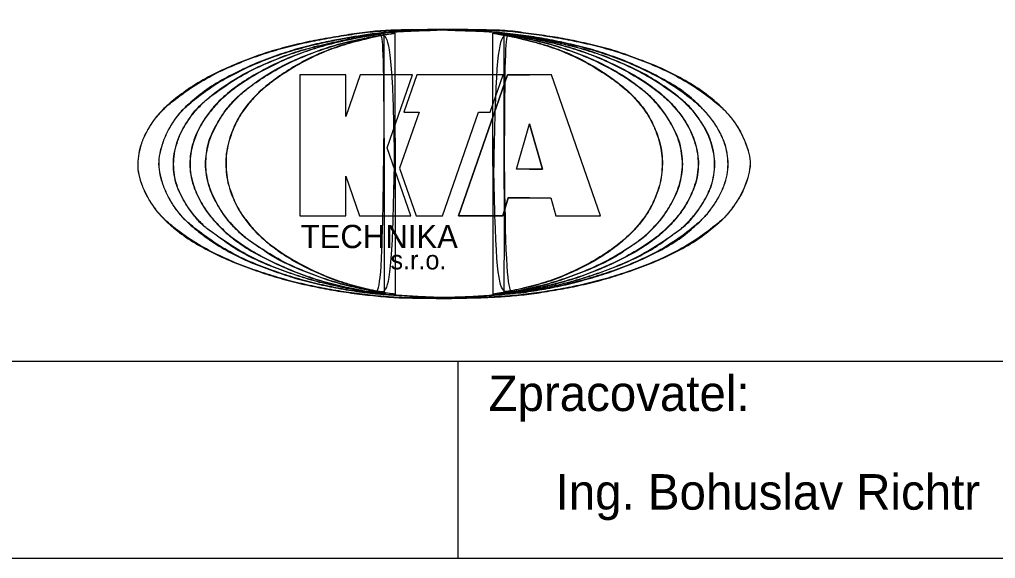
# Model space of a CAD drawing. Extents: x -729968 to -728918, y -1073811 to -1072326.
# Drawn here: x -729327.8 to -729080.2, y -1073351.1 to -1073214.6 of the extents above; entities that cross this region are included whole.
import ezdxf

# ---------------------------------------------------------------- set-up
doc = ezdxf.new("R2010")
doc.units = 0
doc.layers.add('_popis', color=7, linetype='Continuous')
doc.layers.add('Rozpiska_pole_6', color=7, linetype='Continuous')

msp = doc.modelspace()

# ---------------------------------------------------------------- linework, layer by layer
at = {"layer": '_popis'}
for p, q in [((-729198.42, -1073241.01), (-729195.1, -1073252.49)), ((-729195.1, -1073252.49), (-729198.42, -1073252.49))]:
    msp.add_line(p, q, dxfattribs=at)
for points in [[(-729256.7, -1073228.58), (-729256.7, -1073264.29), (-729245.02, -1073264.29), (-729245.02, -1073254.22), (-729241.52, -1073264.29), (-729228.52, -1073264.29), (-729234.52, -1073247.06), (-729228.09, -1073228.58), (-729241.34, -1073228.58), (-729245.02, -1073239.17), (-729245.02, -1073228.58), (-729256.7, -1073228.58)], [(-729256.7, -1073228.58), (-729256.7, -1073264.29), (-729245.02, -1073264.29), (-729245.02, -1073254.22), (-729241.52, -1073264.29), (-729228.52, -1073264.29), (-729234.52, -1073247.06), (-729228.09, -1073228.58), (-729241.34, -1073228.58), (-729245.02, -1073239.17), (-729245.02, -1073228.58), (-729256.7, -1073228.58)], [(-729227.02, -1073228.58), (-729230.3, -1073238.02), (-729226.42, -1073238.02), (-729231.36, -1073252.21), (-729227.16, -1073264.29), (-729220.51, -1073264.29), (-729211.37, -1073238.02), (-729208.35, -1073238.02), (-729205.06, -1073228.58), (-729227.02, -1073228.58)], [(-729227.02, -1073228.58), (-729230.3, -1073238.02), (-729226.42, -1073238.02), (-729231.36, -1073252.21), (-729227.16, -1073264.29), (-729220.51, -1073264.29), (-729211.37, -1073238.02), (-729208.35, -1073238.02), (-729205.06, -1073228.58), (-729227.02, -1073228.58)], [(-729198.42, -1073259.72), (-729203.83, -1073259.72), (-729205.15, -1073264.29), (-729216.42, -1073264.28), (-729203.99, -1073228.58), (-729198.42, -1073228.58)], [(-729198.42, -1073228.58), (-729203.99, -1073228.58), (-729216.42, -1073264.28), (-729205.15, -1073264.29), (-729203.83, -1073259.72), (-729198.42, -1073259.72)], [(-729198.42, -1073259.72), (-729193.01, -1073259.72), (-729191.69, -1073264.29), (-729180.43, -1073264.28), (-729192.85, -1073228.58), (-729198.42, -1073228.58)], [(-729198.42, -1073259.72), (-729193.01, -1073259.72), (-729191.69, -1073264.29), (-729180.43, -1073264.28), (-729192.85, -1073228.58), (-729198.42, -1073228.58)], [(-729198.42, -1073252.49), (-729201.74, -1073252.49), (-729198.42, -1073241.01)], [(-729198.42, -1073252.49), (-729201.74, -1073252.49), (-729198.42, -1073241.01)], [(-729198.42, -1073252.49), (-729195.1, -1073252.49), (-729198.42, -1073241.01)]]:
    msp.add_lwpolyline(points, dxfattribs=at)
for points in [[(-729220.07, -1073217.05), (-729222.09, -1073217.09), (-729225.67, -1073217.14), (-729231.03, -1073217.18), (-729236.17, -1073217.36), (-729241.53, -1073217.93), (-729246.88, -1073218.83), (-729252.26, -1073219.71), (-729257.63, -1073220.87), (-729263.01, -1073222.26), (-729268.39, -1073224.01), (-729273.74, -1073226.17), (-729279.19, -1073228.61), (-729284.59, -1073231.83), (-729288.82, -1073234.98), (-729292.04, -1073237.91), (-729294.02, -1073240.37), (-729295.67, -1073243.1), (-729296.94, -1073245.77), (-729297.53, -1073248.51), (-729297.93, -1073251.2), (-729297.6, -1073253.94), (-729296.75, -1073256.62), (-729295.56, -1073259.36), (-729293.8, -1073262.03), (-729291.93, -1073264.48), (-729288.75, -1073267.34), (-729284.65, -1073270.51), (-729279.15, -1073273.5), (-729273.79, -1073276.04), (-729268.37, -1073278.03), (-729263, -1073279.79), (-729257.64, -1073281.26), (-729252.28, -1073282.42), (-729246.92, -1073283.41), (-729241.53, -1073284.16), (-729236.17, -1073284.75), (-729230.8, -1073285.17), (-729225.44, -1073285.11), (-729220.07, -1073285.3), (-729214.71, -1073285.13), (-729210.61, -1073285.08), (-729208.3, -1073284.96), (-729207.78, -1073284.93)], [(-729220.07, -1073217.05), (-729226.13, -1073217.14), (-729230.79, -1073217.2), (-729236.15, -1073217.42), (-729241.51, -1073217.98), (-729246.87, -1073218.82), (-729252.24, -1073219.75), (-729257.6, -1073220.9), (-729262.96, -1073222.31), (-729268.33, -1073224.06), (-729273.69, -1073226.19), (-729279.02, -1073228.66), (-729284.39, -1073231.83), (-729289.75, -1073235.87), (-729291.84, -1073237.82), (-729294.02, -1073240.51), (-729295.65, -1073243.17), (-729296.86, -1073245.86), (-729297.5, -1073248.53), (-729297.81, -1073251.22), (-729297.53, -1073253.86), (-729296.72, -1073256.57), (-729295.51, -1073259.26), (-729293.83, -1073261.92), (-729291.67, -1073264.62), (-729289.76, -1073266.4), (-729284.4, -1073270.47), (-729279.04, -1073273.5), (-729273.74, -1073275.97), (-729268.32, -1073278.01), (-729262.94, -1073279.76), (-729257.61, -1073281.22), (-729252.28, -1073282.39), (-729246.89, -1073283.38), (-729241.52, -1073284.14), (-729236.13, -1073284.73), (-729230.83, -1073285.09), (-729225.43, -1073285.15), (-729220.07, -1073285.24), (-729214.71, -1073285.15), (-729209.34, -1073285.01), (-729203.98, -1073284.67), (-729198.65, -1073284.17), (-729193.27, -1073283.35), (-729187.91, -1073282.4), (-729182.55, -1073281.2), (-729177.18, -1073279.71), (-729171.82, -1073277.94), (-729166.46, -1073275.87), (-729161.13, -1073273.37), (-729155.73, -1073270.21), (-729150.34, -1073266.03), (-729148.74, -1073264.6), (-729146.64, -1073261.94), (-729144.87, -1073259.28), (-729143.63, -1073256.57), (-729142.76, -1073253.91), (-729142.33, -1073251.22), (-729142.65, -1073248.55), (-729143.57, -1073245.85), (-729144.78, -1073243.12), (-729146.38, -1073240.51), (-729148.65, -1073237.82), (-729150.3, -1073236.19), (-729155.72, -1073232), (-729161.08, -1073228.83), (-729166.4, -1073226.29), (-729171.79, -1073224.22), (-729177.18, -1073222.37), (-729182.51, -1073220.96), (-729187.91, -1073219.76), (-729193.3, -1073218.83), (-729198.68, -1073218.07), (-729204, -1073217.4), (-729209.35, -1073217.2), (-729214.7, -1073217.11), (-729220.07, -1073217.05), (-729220.07, -1073217.05), (-729220.07, -1073217.05)], [(-729220.07, -1073217.2), (-729218.28, -1073217.27), (-729214.7, -1073217.42), (-729209.33, -1073217.47), (-729203.98, -1073218.06), (-729198.62, -1073218.74), (-729193.24, -1073219.63), (-729187.89, -1073220.82), (-729182.48, -1073222.1), (-729177.13, -1073223.92), (-729171.72, -1073225.99), (-729166.38, -1073228.63), (-729160.8, -1073231.63), (-729156.69, -1073234.91), (-729153.64, -1073237.96), (-729151.72, -1073240.39), (-729150.07, -1073243.1), (-729148.84, -1073245.79), (-729148.2, -1073248.52), (-729147.97, -1073251.23), (-729148.17, -1073253.96), (-729148.99, -1073256.65), (-729150.19, -1073259.35), (-729151.9, -1073262.03), (-729153.72, -1073264.42), (-729156.81, -1073267.32), (-729160.8, -1073270.61), (-729166.34, -1073273.73), (-729171.75, -1073276.24), (-729177.13, -1073278.32), (-729182.52, -1073280.01), (-729187.88, -1073281.51), (-729193.26, -1073282.62), (-729198.62, -1073283.6), (-729203.99, -1073284.13), (-729209.35, -1073284.58), (-729214.7, -1073284.93), (-729220.07, -1073285.1), (-729225.44, -1073284.9), (-729230.8, -1073284.52), (-729236.17, -1073284.23), (-729241.54, -1073283.59), (-729246.91, -1073282.72), (-729252.27, -1073281.58), (-729257.67, -1073280.25), (-729263, -1073278.41), (-729268.42, -1073276.47), (-729273.85, -1073274), (-729279.24, -1073270.74), (-729283.47, -1073267.52), (-729286.7, -1073264.57), (-729288.63, -1073262.06), (-729290.23, -1073259.33), (-729291.43, -1073256.64), (-729292.18, -1073253.94), (-729292.65, -1073251.22), (-729292.24, -1073248.5), (-729291.54, -1073245.79), (-729290.41, -1073243.09), (-729288.82, -1073240.39), (-729286.89, -1073237.76), (-729283.54, -1073234.78), (-729279.31, -1073231.41), (-729273.76, -1073228.45), (-729268.42, -1073225.86), (-729263.03, -1073223.76), (-729257.65, -1073222.04), (-729252.27, -1073220.67), (-729247.69, -1073219.76), (-729244.11, -1073219.1), (-729240.54, -1073218.53), (-729236.17, -1073217.89), (-729230.8, -1073217.55), (-729225.43, -1073217.33), (-729221.86, -1073217.24), (-729220.07, -1073217.2)], [(-729220.07, -1073217.2), (-729225.43, -1073217.34), (-729230.79, -1073217.57), (-729236.15, -1073217.96), (-729241.51, -1073218.69), (-729243.92, -1073219.08), (-729246.87, -1073219.61), (-729252.24, -1073220.71), (-729257.6, -1073222.09), (-729262.97, -1073223.8), (-729268.33, -1073225.91), (-729273.7, -1073228.46), (-729279.03, -1073231.46), (-729284.39, -1073235.56), (-729286.78, -1073237.81), (-729288.83, -1073240.5), (-729290.37, -1073243.17), (-729291.49, -1073245.87), (-729292.2, -1073248.53), (-729292.5, -1073251.22), (-729292.14, -1073253.9), (-729291.38, -1073256.56), (-729290.2, -1073259.25), (-729288.63, -1073261.94), (-729286.52, -1073264.63), (-729284.39, -1073266.65), (-729279.03, -1073270.74), (-729273.7, -1073273.95), (-729268.34, -1073276.41), (-729262.98, -1073278.41), (-729257.61, -1073280.18), (-729252.25, -1073281.56), (-729246.89, -1073282.68), (-729241.52, -1073283.55), (-729236.16, -1073284.17), (-729230.8, -1073284.53), (-729225.43, -1073284.87), (-729220.07, -1073285.04), (-729214.71, -1073284.9), (-729209.34, -1073284.56), (-729204.01, -1073284.12), (-729198.65, -1073283.53), (-729193.27, -1073282.6), (-729187.92, -1073281.45), (-729182.56, -1073279.99), (-729177.18, -1073278.28), (-729171.82, -1073276.2), (-729166.46, -1073273.71), (-729161.09, -1073270.57), (-729155.73, -1073266.29), (-729154.02, -1073264.62), (-729151.89, -1073261.93), (-729150.23, -1073259.26), (-729149.02, -1073256.57), (-729148.27, -1073253.91), (-729148.04, -1073251.24), (-729148.27, -1073248.54), (-729148.91, -1073245.88), (-729150.09, -1073243.19), (-729151.72, -1073240.5), (-729153.85, -1073237.81), (-729155.73, -1073235.91), (-729161.09, -1073231.67), (-729166.46, -1073228.63), (-729171.82, -1073226.05), (-729177.18, -1073223.95), (-729182.55, -1073222.17), (-729187.9, -1073220.83), (-729193.26, -1073219.68), (-729198.64, -1073218.77), (-729203.99, -1073218.07), (-729209.34, -1073217.56), (-729214.7, -1073217.39), (-729220.07, -1073217.2), (-729220.07, -1073217.2), (-729220.07, -1073217.2)], [(-729235.26, -1073284.04), (-729236.28, -1073283.96), (-729238.39, -1073283.79), (-729242.28, -1073283.19), (-729246.92, -1073282.23), (-729252.35, -1073281.08), (-729257.69, -1073279.37), (-729263.08, -1073277.51), (-729268.47, -1073275.18), (-729273.95, -1073272.24), (-729277.75, -1073269.24), (-729281.14, -1073267.01), (-729283.15, -1073264.75), (-729285.19, -1073262.02), (-729286.78, -1073259.33), (-729288.02, -1073256.67), (-729288.56, -1073253.92), (-729288.86, -1073251.22), (-729288.57, -1073248.51), (-729287.95, -1073245.8), (-729286.91, -1073243.04), (-729285.24, -1073240.43), (-729283.33, -1073237.59), (-729281.13, -1073235.48), (-729277.93, -1073232.87), (-729273.9, -1073230.04), (-729268.46, -1073226.98), (-729263.03, -1073224.71), (-729257.69, -1073222.67), (-729252.28, -1073221.22), (-729246.87, -1073220), (-729241.52, -1073218.94), (-729237.65, -1073218.25), (-729235.56, -1073218.12), (-729235.28, -1073218.1)], [(-729235.26, -1073284.04), (-729238.33, -1073283.75), (-729241.54, -1073283.28), (-729246.9, -1073282.23), (-729252.29, -1073281), (-729257.67, -1073279.35), (-729263, -1073277.46), (-729268.34, -1073275.15), (-729273.72, -1073272.17), (-729279.11, -1073268.36), (-729280.55, -1073267.33), (-729283.18, -1073264.63), (-729285.21, -1073261.88), (-729286.76, -1073259.26), (-729287.92, -1073256.6), (-729288.53, -1073253.88), (-729288.77, -1073251.2), (-729288.53, -1073248.58), (-729287.9, -1073245.85), (-729286.85, -1073243.15), (-729285.27, -1073240.49), (-729283.35, -1073237.81), (-729280.62, -1073235.08), (-729279.14, -1073233.87), (-729273.72, -1073230.05), (-729268.3, -1073227.03), (-729262.96, -1073224.71), (-729257.68, -1073222.77), (-729252.19, -1073221.24), (-729246.88, -1073220.03), (-729241.49, -1073218.95), (-729236.12, -1073218.16), (-729235.28, -1073218.1), (-729235.26, -1073284.04), (-729235.28, -1073218.1)], [(-729235.28, -1073218.1), (-729237.21, -1073218.39), (-729241.1, -1073218.98), (-729246.77, -1073220.14), (-729252.3, -1073221.67), (-729257.71, -1073223.45), (-729263.06, -1073225.82), (-729268.47, -1073228.65), (-729273.21, -1073231.75), (-729276.94, -1073234.86), (-729279.41, -1073237.71), (-729281.36, -1073240.38), (-729282.8, -1073243.08), (-729283.84, -1073245.8), (-729284.46, -1073248.52), (-729284.64, -1073251.23), (-729284.44, -1073253.94), (-729283.76, -1073256.65), (-729282.61, -1073259.31), (-729281.2, -1073262.07), (-729279.18, -1073264.71), (-729276.73, -1073267.5), (-729273.14, -1073270.6), (-729268.47, -1073273.64), (-729263.04, -1073276.37), (-729257.65, -1073278.66), (-729252.3, -1073280.58), (-729246.91, -1073282.01), (-729242.05, -1073283), (-729238.17, -1073283.65), (-729236.07, -1073283.93), (-729235.26, -1073284.04)], [(-729235.28, -1073218.1), (-729241.06, -1073219.02), (-729246.87, -1073220.23), (-729252.26, -1073221.7), (-729257.64, -1073223.53), (-729262.95, -1073225.84), (-729268.31, -1073228.67), (-729273.69, -1073232.24), (-729277.05, -1073235.13), (-729279.45, -1073237.83), (-729281.34, -1073240.49), (-729282.76, -1073243.14), (-729283.79, -1073245.86), (-729284.39, -1073248.56), (-729284.58, -1073251.22), (-729284.37, -1073253.92), (-729283.71, -1073256.57), (-729282.6, -1073259.25), (-729281.16, -1073261.96), (-729279.21, -1073264.61), (-729276.82, -1073267.28), (-729273.64, -1073270.07), (-729268.33, -1073273.59), (-729262.94, -1073276.35), (-729257.59, -1073278.63), (-729252.23, -1073280.52), (-729246.89, -1073281.96), (-729241.51, -1073283.07), (-729237.7, -1073283.7), (-729235.26, -1073284.04), (-729235.28, -1073218.1), (-729235.26, -1073284.04)], [(-729232.46, -1073284.13), (-729233.7, -1073284.02), (-729236.75, -1073283.76), (-729241.53, -1073282.73), (-729246.94, -1073281.52), (-729252.28, -1073279.67), (-729257.69, -1073277.59), (-729263.18, -1073274.99), (-729267.22, -1073272.12), (-729270.8, -1073269.76), (-729273.17, -1073267.41), (-729275.61, -1073264.79), (-729277.26, -1073261.97), (-729278.8, -1073259.35), (-729279.84, -1073256.65), (-729280.41, -1073253.94), (-729280.7, -1073251.23), (-729280.38, -1073248.53), (-729279.96, -1073245.79), (-729278.85, -1073243.11), (-729277.42, -1073240.44), (-729275.68, -1073237.69), (-729273.41, -1073234.94), (-729270.84, -1073232.66), (-729267.35, -1073230.03), (-729263.13, -1073227.27), (-729257.7, -1073224.6), (-729252.31, -1073222.51), (-729246.95, -1073220.74), (-729241.55, -1073219.52), (-729236.74, -1073218.52), (-729233.69, -1073218.17), (-729232.46, -1073218.03)], [(-729232.46, -1073284.13), (-729236.15, -1073283.75), (-729241.54, -1073282.72), (-729246.85, -1073281.44), (-729252.24, -1073279.65), (-729257.61, -1073277.54), (-729262.95, -1073274.91), (-729268.32, -1073271.4), (-729270.34, -1073269.99), (-729273.26, -1073267.28), (-729275.58, -1073264.63), (-729277.29, -1073261.93), (-729278.76, -1073259.25), (-729279.78, -1073256.57), (-729280.36, -1073253.95), (-729280.6, -1073251.23), (-729280.36, -1073248.52), (-729279.86, -1073245.87), (-729278.84, -1073243.21), (-729277.39, -1073240.47), (-729275.68, -1073237.82), (-729273.45, -1073235.13), (-729270.51, -1073232.45), (-729268.3, -1073230.77), (-729262.95, -1073227.31), (-729257.62, -1073224.66), (-729252.23, -1073222.53), (-729246.91, -1073220.82), (-729241.54, -1073219.53), (-729236.15, -1073218.5), (-729232.46, -1073218.03), (-729232.46, -1073284.13), (-729232.46, -1073218.03)], [(-729232.46, -1073218.03), (-729233.69, -1073218.21), (-729236.74, -1073218.65), (-729241.54, -1073219.84), (-729246.97, -1073221.28), (-729252.37, -1073223.39), (-729257.76, -1073226.16), (-729262.49, -1073229.25), (-729266.36, -1073232.23), (-729269.06, -1073235.02), (-729271.19, -1073237.7), (-729272.81, -1073240.41), (-729273.97, -1073243.13), (-729274.84, -1073245.82), (-729275.4, -1073248.51), (-729275.48, -1073251.22), (-729275.32, -1073253.92), (-729274.8, -1073256.63), (-729273.84, -1073259.3), (-729272.66, -1073262.03), (-729270.97, -1073264.7), (-729268.84, -1073267.42), (-729266.14, -1073270.08), (-729262.46, -1073273.14), (-729257.77, -1073276.07), (-729252.35, -1073278.74), (-729246.98, -1073280.94), (-729241.56, -1073282.44), (-729236.72, -1073283.45), (-729233.7, -1073283.93), (-729232.46, -1073284.13)], [(-729232.46, -1073218.03), (-729236.15, -1073218.62), (-729241.5, -1073219.85), (-729246.89, -1073221.37), (-729252.24, -1073223.44), (-729257.61, -1073226.2), (-729262.96, -1073229.68), (-729266.48, -1073232.48), (-729269.09, -1073235.14), (-729271.19, -1073237.83), (-729272.77, -1073240.49), (-729273.94, -1073243.18), (-729274.8, -1073245.86), (-729275.32, -1073248.55), (-729275.44, -1073251.21), (-729275.27, -1073253.9), (-729274.74, -1073256.59), (-729273.83, -1073259.25), (-729272.63, -1073261.93), (-729270.96, -1073264.62), (-729268.88, -1073267.25), (-729266.19, -1073269.95), (-729262.97, -1073272.62), (-729257.62, -1073276.04), (-729252.25, -1073278.71), (-729246.9, -1073280.85), (-729241.49, -1073282.4), (-729236.15, -1073283.51), (-729232.46, -1073284.13), (-729232.46, -1073218.03), (-729232.46, -1073284.13)], [(-729207.78, -1073284.93), (-729206.52, -1073284.86), (-729203.47, -1073284.64), (-729198.61, -1073284.24), (-729193.27, -1073283.36), (-729187.89, -1073282.45), (-729182.52, -1073281.23), (-729177.14, -1073279.75), (-729171.77, -1073277.97), (-729166.39, -1073275.91), (-729160.98, -1073273.39), (-729155.47, -1073270.26), (-729151.54, -1073267.04), (-729148.37, -1073264.39), (-729146.68, -1073261.99), (-729144.81, -1073259.4), (-729143.61, -1073256.64), (-729142.7, -1073253.95), (-729142.19, -1073251.24), (-729142.55, -1073248.46), (-729143.58, -1073245.8), (-729144.72, -1073243.06), (-729146.4, -1073240.33), (-729148.35, -1073238.08), (-729151.36, -1073235.11), (-729155.48, -1073232), (-729160.95, -1073228.81), (-729166.33, -1073226.22), (-729171.76, -1073224.22), (-729177.09, -1073222.29), (-729182.51, -1073220.95), (-729187.88, -1073219.7), (-729193.29, -1073218.8), (-729198.66, -1073218.1), (-729203.99, -1073217.27), (-729209.35, -1073217.21), (-729214.71, -1073217.09), (-729218.28, -1073217.07), (-729220.07, -1073217.05)], [(-729207.68, -1073284.13), (-729206.45, -1073284.02), (-729203.39, -1073283.76), (-729198.61, -1073282.73), (-729193.2, -1073281.52), (-729187.86, -1073279.67), (-729182.45, -1073277.59), (-729176.97, -1073274.99), (-729172.93, -1073272.12), (-729169.34, -1073269.76), (-729166.97, -1073267.41), (-729164.54, -1073264.79), (-729162.88, -1073261.97), (-729161.34, -1073259.35), (-729160.31, -1073256.65), (-729159.74, -1073253.94), (-729159.44, -1073251.23), (-729159.76, -1073248.53), (-729160.19, -1073245.79), (-729161.29, -1073243.11), (-729162.73, -1073240.44), (-729164.47, -1073237.69), (-729166.74, -1073234.94), (-729169.3, -1073232.66), (-729172.79, -1073230.03), (-729177.01, -1073227.27), (-729182.44, -1073224.6), (-729187.83, -1073222.51), (-729193.19, -1073220.74), (-729198.59, -1073219.52), (-729203.4, -1073218.52), (-729206.45, -1073218.17), (-729207.68, -1073218.03)], [(-729207.68, -1073218.03), (-729206.45, -1073218.21), (-729203.4, -1073218.65), (-729198.6, -1073219.84), (-729193.18, -1073221.28), (-729187.77, -1073223.39), (-729182.38, -1073226.16), (-729177.65, -1073229.25), (-729173.79, -1073232.23), (-729171.08, -1073235.02), (-729168.95, -1073237.7), (-729167.34, -1073240.41), (-729166.17, -1073243.13), (-729165.31, -1073245.82), (-729164.74, -1073248.51), (-729164.66, -1073251.22), (-729164.82, -1073253.92), (-729165.34, -1073256.63), (-729166.3, -1073259.3), (-729167.48, -1073262.03), (-729169.17, -1073264.7), (-729171.31, -1073267.42), (-729174.01, -1073270.08), (-729177.69, -1073273.14), (-729182.38, -1073276.07), (-729187.79, -1073278.74), (-729193.17, -1073280.94), (-729198.59, -1073282.44), (-729203.42, -1073283.45), (-729206.45, -1073283.93), (-729207.68, -1073284.13)], [(-729207.68, -1073218.03), (-729203.99, -1073218.62), (-729198.64, -1073219.85), (-729193.26, -1073221.37), (-729187.9, -1073223.44), (-729182.54, -1073226.2), (-729177.18, -1073229.68), (-729173.66, -1073232.48), (-729171.06, -1073235.14), (-729168.95, -1073237.83), (-729167.37, -1073240.49), (-729166.2, -1073243.18), (-729165.35, -1073245.86), (-729164.82, -1073248.55), (-729164.7, -1073251.21), (-729164.88, -1073253.9), (-729165.4, -1073256.59), (-729166.31, -1073259.25), (-729167.51, -1073261.93), (-729169.18, -1073264.62), (-729171.26, -1073267.25), (-729173.96, -1073269.95), (-729177.17, -1073272.62), (-729182.53, -1073276.04), (-729187.89, -1073278.71), (-729193.24, -1073280.85), (-729198.66, -1073282.4), (-729203.99, -1073283.51), (-729207.68, -1073284.13), (-729207.68, -1073218.03), (-729207.68, -1073284.13)], [(-729207.68, -1073284.13), (-729203.99, -1073283.75), (-729198.61, -1073282.72), (-729193.3, -1073281.44), (-729187.91, -1073279.65), (-729182.53, -1073277.54), (-729177.2, -1073274.91), (-729171.82, -1073271.4), (-729169.8, -1073269.99), (-729166.88, -1073267.28), (-729164.57, -1073264.63), (-729162.86, -1073261.93), (-729161.39, -1073259.25), (-729160.36, -1073256.57), (-729159.78, -1073253.95), (-729159.54, -1073251.23), (-729159.78, -1073248.52), (-729160.28, -1073245.87), (-729161.3, -1073243.21), (-729162.75, -1073240.47), (-729164.46, -1073237.82), (-729166.69, -1073235.13), (-729169.64, -1073232.45), (-729171.85, -1073230.77), (-729177.19, -1073227.31), (-729182.52, -1073224.66), (-729187.91, -1073222.53), (-729193.24, -1073220.82), (-729198.6, -1073219.53), (-729204, -1073218.5), (-729207.68, -1073218.03), (-729207.68, -1073284.13), (-729207.68, -1073218.03)], [(-729204.86, -1073218.1), (-729202.93, -1073218.39), (-729199.05, -1073218.98), (-729193.37, -1073220.14), (-729187.84, -1073221.67), (-729182.43, -1073223.45), (-729177.08, -1073225.82), (-729171.67, -1073228.65), (-729166.93, -1073231.75), (-729163.21, -1073234.86), (-729160.73, -1073237.71), (-729158.79, -1073240.38), (-729157.34, -1073243.08), (-729156.3, -1073245.8), (-729155.69, -1073248.52), (-729155.5, -1073251.23), (-729155.7, -1073253.94), (-729156.38, -1073256.65), (-729157.53, -1073259.31), (-729158.94, -1073262.07), (-729160.96, -1073264.71), (-729163.41, -1073267.5), (-729167, -1073270.6), (-729171.67, -1073273.64), (-729177.11, -1073276.37), (-729182.49, -1073278.66), (-729187.84, -1073280.58), (-729193.23, -1073282.01), (-729198.09, -1073283), (-729201.98, -1073283.65), (-729204.07, -1073283.93), (-729204.88, -1073284.04)], [(-729204.88, -1073284.04), (-729203.86, -1073283.96), (-729201.75, -1073283.79), (-729197.87, -1073283.19), (-729193.22, -1073282.23), (-729187.8, -1073281.08), (-729182.46, -1073279.37), (-729177.07, -1073277.51), (-729171.67, -1073275.18), (-729166.2, -1073272.24), (-729162.39, -1073269.24), (-729159, -1073267.01), (-729156.99, -1073264.75), (-729154.95, -1073262.02), (-729153.36, -1073259.33), (-729152.13, -1073256.67), (-729151.58, -1073253.92), (-729151.28, -1073251.22), (-729151.57, -1073248.51), (-729152.19, -1073245.8), (-729153.23, -1073243.04), (-729154.9, -1073240.43), (-729156.82, -1073237.59), (-729159.01, -1073235.48), (-729162.21, -1073232.87), (-729166.25, -1073230.04), (-729171.68, -1073226.98), (-729177.11, -1073224.71), (-729182.46, -1073222.67), (-729187.86, -1073221.22), (-729193.27, -1073220), (-729198.62, -1073218.94), (-729202.5, -1073218.25), (-729204.58, -1073218.12), (-729204.86, -1073218.1)], [(-729204.88, -1073284.04), (-729201.81, -1073283.75), (-729198.6, -1073283.28), (-729193.24, -1073282.23), (-729187.85, -1073281), (-729182.48, -1073279.35), (-729177.14, -1073277.46), (-729171.8, -1073275.15), (-729166.43, -1073272.17), (-729161.04, -1073268.36), (-729159.59, -1073267.33), (-729156.96, -1073264.63), (-729154.93, -1073261.88), (-729153.38, -1073259.26), (-729152.22, -1073256.6), (-729151.61, -1073253.88), (-729151.38, -1073251.2), (-729151.61, -1073248.58), (-729152.24, -1073245.85), (-729153.3, -1073243.15), (-729154.87, -1073240.49), (-729156.79, -1073237.81), (-729159.53, -1073235.08), (-729161, -1073233.87), (-729166.43, -1073230.05), (-729171.84, -1073227.03), (-729177.18, -1073224.71), (-729182.47, -1073222.77), (-729187.95, -1073221.24), (-729193.26, -1073220.03), (-729198.65, -1073218.95), (-729204.02, -1073218.16), (-729204.86, -1073218.1), (-729204.88, -1073284.04), (-729204.86, -1073218.1)], [(-729204.86, -1073218.1), (-729199.08, -1073219.02), (-729193.27, -1073220.23), (-729187.88, -1073221.7), (-729182.5, -1073223.53), (-729177.19, -1073225.84), (-729171.83, -1073228.67), (-729166.45, -1073232.24), (-729163.09, -1073235.13), (-729160.7, -1073237.83), (-729158.8, -1073240.49), (-729157.38, -1073243.14), (-729156.36, -1073245.86), (-729155.75, -1073248.56), (-729155.57, -1073251.22), (-729155.78, -1073253.92), (-729156.43, -1073256.57), (-729157.54, -1073259.25), (-729158.98, -1073261.96), (-729160.93, -1073264.61), (-729163.33, -1073267.28), (-729166.51, -1073270.07), (-729171.82, -1073273.59), (-729177.2, -1073276.35), (-729182.56, -1073278.63), (-729187.92, -1073280.52), (-729193.25, -1073281.96), (-729198.63, -1073283.07), (-729202.44, -1073283.7), (-729204.88, -1073284.04), (-729204.86, -1073218.1), (-729204.88, -1073284.04)]]:
    msp.add_open_spline(points, degree=3, dxfattribs=at)
at = {"layer": 'Rozpiska_pole_6'}
for p, q in [((-729868.27, -1073301.15), (-729018.27, -1073301.15)), ((-729216.52, -1073351.15), (-729216.52, -1073301.15))]:
    msp.add_line(p, q, dxfattribs=at)
msp.add_lwpolyline([(-729868.27, -1073101.15), (-729018.27, -1073101.15), (-729018.27, -1073351.15), (-729868.27, -1073351.15)], close=True, dxfattribs=at)

# ---------------------------------------------------------------- texts
at = {"layer": '_popis'}
for s, height, p in [('TECHNIKA', 5.898, (-729256.46, -1073272.49)), ('s.r.o.', 4.772, (-729233.67, -1073277.88))]:
    msp.add_text(s, height=height, dxfattribs=at).set_placement(p)
at = {"layer": 'Rozpiska_pole_6'}
for s, p in [('Zpracovatel:', (-729208.79, -1073313.78)), ('Ing. Bohuslav Richtr', (-729191.79, -1073338.78))]:
    msp.add_text(s, height=9, dxfattribs=at).set_placement(p)

doc.saveas('drawing.dxf')
